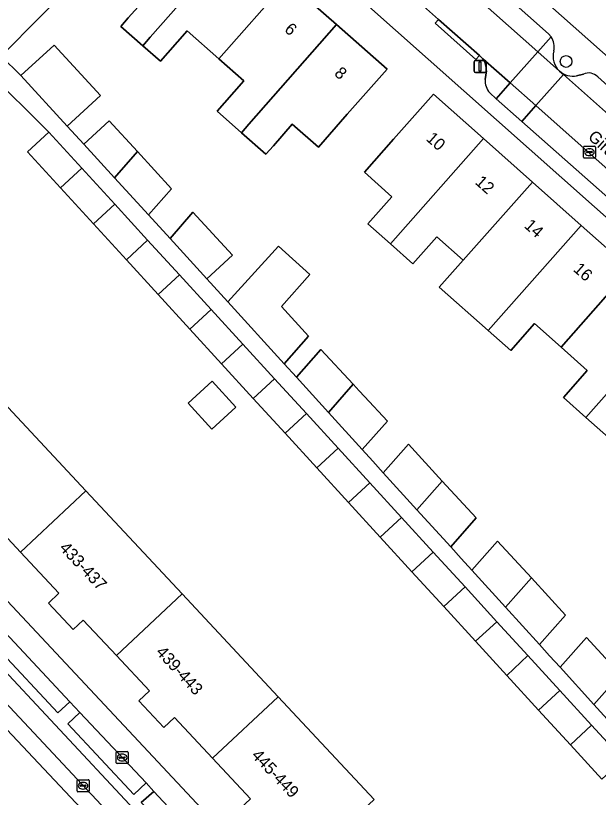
# Model space of a CAD drawing. Extents: x 163147 to 163550, y 380933 to 381639.
# Drawn here: x 163333 to 163381.5, y 381026.8 to 381091.7 of the extents above; entities that cross this region are included whole.
import ezdxf

# ---------------------------------------------------------------- set-up
doc = ezdxf.new("R2010")
doc.units = 0
for name, color, linetype in [('IMGEO_Berm_groen', 7, 'Continuous'), ('IMGEO_Boom', 7, 'Continuous'), ('IMGEO_Erf', 7, 'Continuous'), ('IMGEO_Fietspad_gesloten', 7, 'Continuous'), ('IMGEO_Kolk', 7, 'Continuous'), ('IMGEO_Lichtmast', 7, 'Continuous'), ('IMGEO_Openbare_ruimte_label', 7, 'Continuous'), ('IMGEO_Pand', 7, 'Continuous'), ('IMGEO_Pand_nummerreeks', 7, 'Continuous'), ('IMGEO_Parkeervlak_open', 7, 'Continuous'), ('IMGEO_Rijbaan_lokaal_gesloten', 7, 'Continuous'), ('IMGEO_Rijbaan_lokaal_open', 7, 'Continuous'), ('IMGEO_Voetpad_open', 7, 'Continuous')]:
    doc.layers.add(name, color=color, linetype=linetype)

msp = doc.modelspace()

# ---------------------------------------------------------------- linework, layer by layer
at = {"layer": 'IMGEO_Berm_groen'}
msp.add_lwpolyline([(163330.888, 381039.205), (163331.213, 381038.824), (163331.547, 381039.08), (163336.526, 381033.765), (163337.548, 381034.692), (163326.013, 381046.997)], dxfattribs=at)
for points in [[(163338.375, 381033.79), (163337.38, 381032.862), (163342.851, 381027.002), (163343.87, 381027.948)], [(163344.515, 381027.25), (163343.471, 381026.337), (163347.031, 381022.522), (163348.067, 381023.459)]]:
    msp.add_lwpolyline(points, close=True, dxfattribs=at)
at = {"layer": 'IMGEO_Boom'}
msp.add_circle((163378.776, 381087.858), 0.489, dxfattribs=at)
at = {"layer": 'IMGEO_Erf'}
for points in [[(163348.475, 381118.157), (163412.679, 381061.277), (163413.36, 381064.962), (163417.698, 381085.92), (163417.846, 381087.332), (163416.123, 381085.594), (163413.144, 381088.297), (163415.16, 381090.565), (163414.131, 381091.494), (163413.141, 381092.387), (163411.13, 381090.125), (163408.025, 381092.942), (163405.283, 381095.431), (163407.28, 381097.676), (163404.687, 381100.016), (163402.696, 381097.778), (163397.399, 381102.584), (163394.382, 381105.322), (163396.345, 381107.544), (163395.338, 381108.453), (163394.328, 381109.364), (163392.37, 381107.148), (163389.354, 381109.884)], [(163430.25, 381032.233), (163348.313, 381104.939), (163331.837, 381088.308), (163333.467, 381086.693), (163336.232, 381089.226), (163340.081, 381085.022), (163337.316, 381082.489), (163338.69, 381080.991), (163340.809, 381082.934), (163343.154, 381080.377), (163345.983, 381077.292), (163344.075, 381075.12), (163345.862, 381073.171), (163347.771, 381075.343), (163351.052, 381071.765), (163348.934, 381069.822), (163350.666, 381067.909), (163354.867, 381072.511), (163357.472, 381070.168), (163355.138, 381067.521), (163357.381, 381065.055), (163355.349, 381062.761), (163356.361, 381061.648), (163358.4, 381063.95), (163361.091, 381061.051), (163361.587, 381060.513), (163362.025, 381060.038), (163363.922, 381057.978), (163361.838, 381055.626), (163362.702, 381054.676), (163363.586, 381053.704), (163365.68, 381056.068), (163368.491, 381053.016), (163371.314, 381049.951), (163369.185, 381047.549), (163370.056, 381046.591), (163370.936, 381045.623), (163373.076, 381048.037), (163375.889, 381044.982), (163378.733, 381041.894), (163376.56, 381039.44), (163377.41, 381038.506), (163378.274, 381037.556), (163380.458, 381040.021), (163383.287, 381036.948)], [(163381.753, 381028.252), (163379.129, 381031.116), (163376.494, 381033.993), (163373.847, 381036.882), (163371.254, 381039.713), (163368.606, 381042.603), (163365.959, 381045.492), (163363.327, 381048.366), (163360.694, 381051.239), (163358.062, 381054.112), (163355.423, 381056.993), (163352.785, 381059.872), (163350.147, 381062.752), (163347.508, 381065.632), (163344.871, 381068.511), (163342.234, 381071.389), (163339.496, 381074.378), (163336.759, 381077.366), (163334.022, 381080.354), (163335.792, 381081.975), (163330.63, 381087.089)], [(163382.293, 381056.632), (163380.425, 381058.292), (163378.555, 381059.952), (163380.539, 381062.191), (163378.353, 381064.145), (163376.159, 381066.094), (163374.17, 381063.849), (163372.301, 381065.509), (163368.238, 381069.118), (163370.229, 381071.362), (163368.036, 381073.31), (163366.047, 381071.065), (163364.178, 381072.725), (163362.309, 381074.385), (163364.298, 381076.631), (163362.014, 381078.66), (163364.444, 381081.399), (163367.761, 381085.139), (163371.914, 381081.455), (163375.978, 381077.849), (163380.041, 381074.245), (163384.106, 381070.638)], [(163330.871, 381060.763), (163338.872, 381052.207), (163346.873, 381043.65), (163354.856, 381035.112), (163362.831, 381026.582)]]:
    msp.add_lwpolyline(points, dxfattribs=at)
for points in [[(163358.198, 381080.749), (163356.026, 381082.658), (163354.449, 381080.863), (163353.835, 381080.164), (163351.809, 381081.943), (163349.777, 381083.729), (163350.394, 381084.431), (163351.995, 381086.253), (163349.921, 381088.076), (163347.275, 381090.401), (163345.676, 381088.581), (163345.057, 381087.876), (163343.596, 381089.159), (163341.77, 381090.764), (163342.391, 381091.471), (163344.009, 381093.312), (163341.641, 381095.393), (163347.291, 381101.823), (163351.485, 381098.137), (163355.592, 381094.529), (163359.698, 381090.921), (163363.895, 381087.233), (163360.595, 381083.477)], [(163347.36, 381059.482), (163349.367, 381061.32), (163351.344, 381059.162), (163349.337, 381057.324)]]:
    msp.add_lwpolyline(points, close=True, dxfattribs=at)
at = {"layer": 'IMGEO_Fietspad_gesloten'}
for points in [[(163431.634, 380936.983), (163426.381, 380942.59), (163389.734, 380981.756), (163386.168, 380985.564), (163372.648, 381000), (163319.829, 381056.397), (163310.14, 381066.773), (163306.558, 381070.608), (163278.278, 381100.892), (163188.415, 381197.241)], [(163300.254, 381074.541), (163308.689, 381065.5), (163311.897, 381062.058), (163312.543, 381061.369), (163314.772, 381058.98), (163315.706, 381057.986), (163318.395, 381055.109), (163325.365, 381047.696), (163326.013, 381046.997), (163337.548, 381034.692), (163338.375, 381033.79), (163343.87, 381027.948), (163344.515, 381027.25), (163348.067, 381023.459), (163348.514, 381022.981), (163356.522, 381014.433), (163357.127, 381013.723), (163365.262, 381005.053), (163366.186, 381004.068), (163370.003, 381000), (163371.64, 380998.255), (163372.278, 380997.54), (163377.885, 380991.559)]]:
    msp.add_lwpolyline(points, dxfattribs=at)
at = {"layer": 'IMGEO_Kolk'}
for p, q in [((163380.216, 381079.904), (163380.216, 381080.756)), ((163380.291, 381080.83), (163381.143, 381080.83)), ((163380.704, 381080.61), (163380.729, 381080.61)), ((163381.217, 381080.756), (163381.217, 381079.904)), ((163381.143, 381079.83), (163380.291, 381079.83)), ((163380.475, 381080.324), (163380.475, 381080.336)), ((163380.913, 381080.287), (163380.515, 381080.287)), ((163380.518, 381080.373), (163380.916, 381080.373)), ((163380.727, 381080.05), (163380.702, 381080.05)), ((163380.959, 381080.336), (163380.959, 381080.324)), ((163341.386, 381029.629), (163341.386, 381030.481)), ((163341.461, 381030.555), (163342.313, 381030.555)), ((163342.387, 381030.481), (163342.387, 381029.629)), ((163341.645, 381030.049), (163341.645, 381030.061)), ((163342.083, 381030.012), (163341.685, 381030.012)), ((163341.688, 381030.098), (163342.086, 381030.098)), ((163341.897, 381029.775), (163341.872, 381029.775)), ((163341.874, 381030.335), (163341.899, 381030.335)), ((163342.129, 381030.061), (163342.129, 381030.049)), ((163342.313, 381029.555), (163341.461, 381029.555)), ((163338.132, 381027.293), (163338.132, 381028.145)), ((163338.207, 381028.219), (163339.059, 381028.219)), ((163338.62, 381027.999), (163338.645, 381027.999)), ((163339.133, 381028.145), (163339.133, 381027.293)), ((163339.059, 381027.219), (163338.207, 381027.219)), ((163338.391, 381027.713), (163338.391, 381027.725)), ((163338.829, 381027.676), (163338.431, 381027.676)), ((163338.434, 381027.762), (163338.832, 381027.762)), ((163338.643, 381027.439), (163338.618, 381027.439)), ((163338.875, 381027.725), (163338.875, 381027.713))]:
    msp.add_line(p, q, dxfattribs=at)
for points in [[(163380.216, 381079.904), (163380.216, 381080.756)], [(163380.291, 381080.83), (163381.143, 381080.83)], [(163381.217, 381080.756), (163381.217, 381079.904)], [(163381.143, 381079.83), (163380.291, 381079.83)], [(163341.386, 381029.629), (163341.386, 381030.481)], [(163341.461, 381030.555), (163342.313, 381030.555)], [(163342.387, 381030.481), (163342.387, 381029.629)], [(163342.313, 381029.555), (163341.461, 381029.555)], [(163338.132, 381027.293), (163338.132, 381028.145)], [(163338.207, 381028.219), (163339.059, 381028.219)], [(163339.133, 381028.145), (163339.133, 381027.293)], [(163339.059, 381027.219), (163338.207, 381027.219)]]:
    msp.add_lwpolyline(points, dxfattribs=at)
for centre, radius, start, end in [((163380.293, 381080.754), 0.0765, 91.55205, 178.44795), ((163380.293, 381080.754), 0.0765, 91.55205, 178.44795), ((163381.141, 381080.754), 0.0765, 1.55205, 88.44795), ((163381.141, 381080.754), 0.0765, 1.55205, 88.44795), ((163380.293, 381079.906), 0.0765, 181.55205, 268.44795), ((163380.293, 381079.906), 0.0765, 181.55205, 268.44795), ((163380.515, 381080.333), 0.0403, 85.87752, 175.75265), ((163380.512, 381080.323), 0.0366, 178.93798, 274.71019), ((163380.916, 381080.33), 0.043, 264.86636, 352.45326), ((163380.92, 381080.335), 0.0386, 1.73085, 96.63898), ((163381.141, 381079.906), 0.0765, 271.55205, 358.44795), ((163381.141, 381079.906), 0.0765, 271.55205, 358.44795), ((163341.463, 381030.479), 0.0765, 91.55205, 178.44795), ((163341.463, 381030.479), 0.0765, 91.55205, 178.44795), ((163342.311, 381030.479), 0.0765, 1.55205, 88.44795), ((163342.311, 381030.479), 0.0765, 1.55205, 88.44795), ((163341.685, 381030.058), 0.0403, 85.87752, 175.75265), ((163341.682, 381030.048), 0.0366, 178.93798, 274.71019), ((163342.086, 381030.055), 0.043, 264.86636, 352.45326), ((163342.09, 381030.06), 0.0386, 1.73085, 96.63898), ((163341.463, 381029.631), 0.0765, 181.55205, 268.44795), ((163341.463, 381029.631), 0.0765, 181.55205, 268.44795), ((163342.311, 381029.631), 0.0765, 271.55205, 358.44795), ((163342.311, 381029.631), 0.0765, 271.55205, 358.44795), ((163338.209, 381028.143), 0.0765, 91.55205, 178.44795), ((163338.209, 381028.143), 0.0765, 91.55205, 178.44795), ((163339.057, 381028.143), 0.0765, 1.55205, 88.44795), ((163339.057, 381028.143), 0.0765, 1.55205, 88.44795), ((163338.209, 381027.295), 0.0765, 181.55205, 268.44795), ((163338.209, 381027.295), 0.0765, 181.55205, 268.44795), ((163338.431, 381027.722), 0.0403, 85.87752, 175.75265), ((163338.428, 381027.712), 0.0366, 178.93798, 274.71019), ((163338.832, 381027.719), 0.043, 264.86636, 352.45326), ((163338.836, 381027.724), 0.0386, 1.73085, 96.63898), ((163339.057, 381027.295), 0.0765, 271.55205, 358.44795), ((163339.057, 381027.295), 0.0765, 271.55205, 358.44795)]:
    msp.add_arc(centre, radius, start, end, dxfattribs=at)
for centre, major_axis, ratio, start_param, end_param in [((163380.703, 381080.33), (-0.387, 0.002), 0.722429, 4.712389, 7.853982), ((163380.728, 381080.33), (-0.39, 0.002), 0.717154, 1.570796, 4.712389), ((163341.873, 381030.055), (-0.387, 0.002), 0.722429, 4.712389, 7.853982), ((163341.898, 381030.055), (-0.39, 0.002), 0.717154, 1.570796, 4.712389), ((163338.619, 381027.719), (-0.387, 0.002), 0.722429, 4.712389, 7.853982), ((163338.644, 381027.719), (-0.39, 0.002), 0.717154, 1.570796, 4.712389)]:
    msp.add_ellipse(centre, major_axis=major_axis, ratio=ratio, start_param=start_param, end_param=end_param, dxfattribs=at)
at = {"layer": 'IMGEO_Lichtmast'}
for p, q in [((163371.134, 381087.042), (163371.134, 381087.842)), ((163371.134, 381087.842), (163371.134, 381087.042)), ((163371.234, 381087.942), (163372.024, 381087.942)), ((163372.024, 381087.942), (163371.234, 381087.942)), ((163372.124, 381087.842), (163372.124, 381087.042)), ((163372.124, 381087.042), (163372.124, 381087.842)), ((163372.024, 381086.942), (163371.234, 381086.942)), ((163371.234, 381086.942), (163372.024, 381086.942))]:
    msp.add_line(p, q, dxfattribs=at)
msp.add_lwpolyline([(163371.554, 381087.817), (163371.704, 381087.817), (163371.704, 381087.067), (163371.554, 381087.067), (163371.554, 381087.817)], dxfattribs=at)
for centre, start, end in [((163371.234, 381087.842), 90, 180), ((163371.234, 381087.842), 90, 180), ((163372.024, 381087.842), 0, 90), ((163372.024, 381087.842), 360, 90), ((163371.234, 381087.042), 180, 270), ((163371.234, 381087.042), 180, 270), ((163372.024, 381087.042), 270, 0), ((163372.024, 381087.042), 270, 0)]:
    msp.add_arc(centre, 0.1, start, end, dxfattribs=at)
at = {"layer": 'IMGEO_Pand'}
for points in [[(163351.485, 381098.137), (163347.291, 381101.823), (163341.641, 381095.393), (163344.009, 381093.312), (163342.391, 381091.471), (163341.77, 381090.764), (163343.596, 381089.159), (163344.217, 381089.866)], [(163355.592, 381094.529), (163351.485, 381098.137), (163344.217, 381089.866), (163343.596, 381089.159), (163345.057, 381087.876), (163345.676, 381088.581), (163347.275, 381090.401), (163349.921, 381088.076)], [(163359.698, 381090.921), (163355.592, 381094.529), (163349.921, 381088.076), (163351.995, 381086.253), (163350.394, 381084.431), (163349.777, 381083.729), (163351.809, 381081.943), (163352.425, 381082.644)], [(163363.895, 381087.233), (163359.698, 381090.921), (163352.425, 381082.644), (163351.809, 381081.943), (163353.835, 381080.164), (163354.449, 381080.863), (163356.026, 381082.658), (163358.198, 381080.749), (163360.595, 381083.477)], [(163337.316, 381082.489), (163340.081, 381085.022), (163336.232, 381089.226), (163333.467, 381086.693)], [(163371.914, 381081.455), (163367.761, 381085.139), (163364.444, 381081.399), (163362.014, 381078.66), (163364.298, 381076.631), (163362.309, 381074.385), (163364.178, 381072.725)], [(163338.69, 381080.991), (163341.246, 381078.204), (163343.154, 381080.377), (163340.809, 381082.934)], [(163338.529, 381078.987), (163335.792, 381081.975), (163334.022, 381080.354), (163336.759, 381077.366)], [(163371.914, 381081.455), (163364.178, 381072.725), (163366.047, 381071.065), (163368.036, 381073.31), (163370.229, 381071.362), (163375.978, 381077.849)], [(163343.154, 381080.377), (163341.246, 381078.204), (163344.075, 381075.12), (163345.983, 381077.292)], [(163338.529, 381078.987), (163336.759, 381077.366), (163339.496, 381074.378), (163341.265, 381076)], [(163380.041, 381074.245), (163375.978, 381077.849), (163370.229, 381071.362), (163368.238, 381069.118), (163372.301, 381065.509)], [(163343.987, 381073.029), (163341.265, 381076), (163339.496, 381074.378), (163342.234, 381071.389)], [(163345.862, 381073.171), (163348.934, 381069.822), (163351.052, 381071.765), (163347.771, 381075.343)], [(163378.353, 381064.145), (163384.106, 381070.638), (163380.041, 381074.245), (163372.301, 381065.509), (163374.17, 381063.849), (163376.159, 381066.094)], [(163343.987, 381073.029), (163342.234, 381071.389), (163344.871, 381068.511), (163346.641, 381070.132)], [(163355.349, 381062.761), (163357.381, 381065.055), (163355.138, 381067.521), (163357.472, 381070.168), (163354.867, 381072.511), (163350.666, 381067.909)], [(163347.508, 381065.632), (163349.278, 381067.253), (163346.641, 381070.132), (163344.871, 381068.511)], [(163388.17, 381067.033), (163384.106, 381070.638), (163378.353, 381064.145), (163380.539, 381062.191), (163378.555, 381059.952), (163380.425, 381058.292)], [(163347.508, 381065.632), (163350.147, 381062.752), (163351.9, 381064.392), (163349.278, 381067.253)], [(163392.234, 381063.427), (163388.17, 381067.033), (163380.425, 381058.292), (163382.293, 381056.632), (163384.486, 381054.683), (163386.476, 381056.929)], [(163352.785, 381059.872), (163354.555, 381061.494), (163351.9, 381064.392), (163350.147, 381062.752)], [(163356.361, 381061.648), (163359.025, 381058.719), (163361.091, 381061.051), (163358.4, 381063.95)], [(163347.36, 381059.482), (163349.337, 381057.324), (163351.344, 381059.162), (163349.367, 381061.32)], [(163355.423, 381056.993), (163357.193, 381058.614), (163354.555, 381061.494), (163352.785, 381059.872)], [(163361.091, 381061.051), (163359.025, 381058.719), (163361.838, 381055.626), (163363.922, 381057.978), (163362.025, 381060.038), (163361.587, 381060.513)], [(163333.43, 381047.117), (163338.872, 381052.207), (163330.871, 381060.763), (163325.396, 381055.643), (163328.142, 381052.706), (163327.264, 381051.885), (163329.318, 381049.688), (163330.229, 381050.54)], [(163355.423, 381056.993), (163358.062, 381054.112), (163359.826, 381055.74), (163357.193, 381058.614)], [(163358.062, 381054.112), (163360.694, 381051.239), (163362.465, 381052.859), (163359.826, 381055.74)], [(163363.586, 381053.704), (163366.379, 381050.633), (163368.491, 381053.016), (163365.68, 381056.068)], [(163363.327, 381048.366), (163365.095, 381049.989), (163362.465, 381052.859), (163360.694, 381051.239)], [(163368.491, 381053.016), (163366.379, 381050.633), (163369.185, 381047.549), (163371.314, 381049.951)], [(163333.43, 381047.117), (163336.63, 381043.695), (163335.755, 381042.877), (163337.807, 381040.681), (163338.657, 381041.476), (163341.405, 381038.537), (163346.873, 381043.65), (163338.872, 381052.207)], [(163363.327, 381048.366), (163365.959, 381045.492), (163367.727, 381047.115), (163365.095, 381049.989)], [(163370.936, 381045.623), (163373.733, 381042.549), (163375.889, 381044.982), (163373.076, 381048.037)], [(163365.959, 381045.492), (163368.606, 381042.603), (163370.376, 381044.224), (163367.727, 381047.115)], [(163375.889, 381044.982), (163373.733, 381042.549), (163376.56, 381039.44), (163378.733, 381041.894)], [(163371.254, 381039.713), (163373.023, 381041.334), (163370.376, 381044.224), (163368.606, 381042.603)], [(163349.398, 381030.01), (163354.856, 381035.112), (163346.873, 381043.65), (163341.405, 381038.537), (163344.153, 381035.598), (163343.274, 381034.776), (163345.357, 381032.548), (163346.247, 381033.38)], [(163375.6, 381038.522), (163373.023, 381041.334), (163371.254, 381039.713), (163373.847, 381036.882)], [(163378.274, 381037.556), (163381.086, 381034.464), (163383.287, 381036.948), (163380.458, 381040.021)], [(163375.6, 381038.522), (163373.847, 381036.882), (163376.494, 381033.993), (163378.264, 381035.614)], [(163383.287, 381036.948), (163381.086, 381034.464), (163383.872, 381031.401), (163386.09, 381033.904)], [(163379.129, 381031.116), (163380.899, 381032.738), (163378.264, 381035.614), (163376.494, 381033.993)], [(163349.398, 381030.01), (163352.55, 381026.639), (163351.626, 381025.775), (163353.708, 381023.549), (163354.593, 381024.376), (163357.335, 381021.443), (163362.831, 381026.582), (163354.856, 381035.112)], [(163379.129, 381031.116), (163381.753, 381028.252), (163383.507, 381029.891), (163380.899, 381032.738)]]:
    msp.add_lwpolyline(points, close=True, dxfattribs=at)
at = {"layer": 'IMGEO_Parkeervlak_open'}
for points in [[(163359.851, 381103.345), (163376.424, 381088.651), (163377.537, 381089.906), (163377.316, 381090.152), (163362.865, 381103.01)], [(163377.537, 381089.906), (163376.424, 381088.651), (163378.234, 381087.046)], [(163372.431, 381085.248), (163372.977, 381084.764), (163374.14, 381086.075), (163371.869, 381088.089)], [(163372.153, 381087.08), (163372.041, 381086.371)], [(163378.234, 381087.046), (163378.55, 381086.767), (163384.78, 381081.243)], [(163380.213, 381086.796), (163379.652, 381086.677)], [(163384.173, 381084.084), (163381.403, 381086.575)], [(163386.023, 381075.538), (163376.265, 381084.191), (163375.103, 381082.881), (163383.185, 381075.72)], [(163317.29, 381050.513), (163364.587, 381000), (163377.34, 380986.38)], [(163348.277, 381019.96), (163330.88, 381038.568)]]:
    msp.add_lwpolyline(points, dxfattribs=at)
msp.add_lwpolyline([(163375.103, 381082.881), (163376.265, 381084.191), (163374.14, 381086.075), (163372.977, 381084.764)], close=True, dxfattribs=at)
for centre, radius, start, end in [((163376.333, 381089.08), 1.46, 346.37955, 34.44554), ((163379.388, 381088.289), 1.696, 164.71974, 227.11731), ((163370.258, 381087.091), 1.895, 359.66853, 31.77176), ((163379.332, 381088.356), 1.71, 230.03822, 280.78913), ((163380.663, 381085.903), 1, 42.24149, 116.71694), ((163373.562, 381086.27), 1.525, 176.20352, 222.09907)]:
    msp.add_arc(centre, radius, start, end, dxfattribs=at)
at = {"layer": 'IMGEO_Rijbaan_lokaal_gesloten'}
msp.add_lwpolyline([(163224.239, 381147.157), (163352.566, 381010.865), (163426.034, 380932.648), (163426.972, 380933.374), (163422.924, 380937.67), (163422.094, 380938.572), (163420.941, 380939.796), (163409.396, 380952.093), (163401.186, 380960.886), (163388.886, 380973.983), (163385.374, 380977.709), (163378.305, 380985.296), (163377.772, 380985.918), (163377.34, 380986.38), (163364.587, 381000), (163317.29, 381050.513), (163315.186, 381052.783), (163313.128, 381055.003), (163312.964, 381055.179), (163310.91, 381057.369), (163306.317, 381062.264), (163305.819, 381062.795), (163299.374, 381069.695)], dxfattribs=at)
at = {"layer": 'IMGEO_Rijbaan_lokaal_open'}
msp.add_lwpolyline([(163351.292, 381106.335), (163354.767, 381103.254), (163365.924, 381093.36), (163368.184, 381091.357), (163371.576, 381088.351), (163371.869, 381088.089), (163374.14, 381086.075), (163376.424, 381088.651), (163359.851, 381103.345), (163359.545, 381103.611), (163357.625, 381105.319), (163346.989, 381114.749)], dxfattribs=at)
for points in [[(163378.55, 381086.767), (163378.234, 381087.046), (163376.424, 381088.651), (163374.14, 381086.075), (163376.265, 381084.191)], [(163384.971, 381081.074), (163384.78, 381081.243), (163378.55, 381086.767), (163376.265, 381084.191), (163386.023, 381075.538), (163387.932, 381073.845), (163402.686, 381060.759), (163402.997, 381060.496), (163406.637, 381057.379), (163408.848, 381059.9), (163408.639, 381060.085), (163389.921, 381076.681), (163388.332, 381078.092)]]:
    msp.add_lwpolyline(points, close=True, dxfattribs=at)
at = {"layer": 'IMGEO_Voetpad_open'}
for points in [[(163429.339, 381046.517), (163420.6, 381054.259), (163418.735, 381055.912), (163415.366, 381058.896), (163413.645, 381060.421), (163412.679, 381061.277), (163348.475, 381118.157)], [(163354.767, 381103.254), (163351.292, 381106.335), (163348.313, 381104.939), (163430.25, 381032.233), (163431.364, 381035.276), (163430.742, 381035.835), (163427.947, 381038.346), (163425.074, 381040.927), (163424.908, 381041.074)], [(163314.628, 381076.045), (163310.339, 381071.71), (163312.93, 381069.222), (163330.63, 381087.089), (163331.837, 381088.308), (163348.313, 381104.939)], [(163362.865, 381103.01), (163377.316, 381090.152), (163377.537, 381089.906)], [(163367.902, 381091.03), (163368.184, 381091.357), (163365.924, 381093.36)], [(163371.869, 381088.089), (163371.576, 381088.351), (163371.288, 381088.025), (163367.902, 381091.03)], [(163383.872, 381031.401), (163381.086, 381034.464), (163378.274, 381037.556), (163377.41, 381038.506), (163376.56, 381039.44), (163373.733, 381042.549), (163370.936, 381045.623), (163370.056, 381046.591), (163369.185, 381047.549), (163366.379, 381050.633), (163363.586, 381053.704), (163362.702, 381054.676), (163361.838, 381055.626), (163359.025, 381058.719), (163356.361, 381061.648), (163355.349, 381062.761), (163350.666, 381067.909), (163348.934, 381069.822), (163345.862, 381073.171), (163344.075, 381075.12), (163341.246, 381078.204), (163338.69, 381080.991), (163337.316, 381082.489), (163333.467, 381086.693), (163331.837, 381088.308)], [(163330.63, 381087.089), (163335.792, 381081.975), (163338.529, 381078.987), (163341.265, 381076), (163343.987, 381073.029), (163346.641, 381070.132), (163349.278, 381067.253), (163351.9, 381064.392), (163354.555, 381061.494), (163357.193, 381058.614), (163359.826, 381055.74), (163362.465, 381052.859), (163365.095, 381049.989), (163367.727, 381047.115), (163370.376, 381044.224), (163373.023, 381041.334), (163375.6, 381038.522), (163378.264, 381035.614), (163380.899, 381032.738), (163383.507, 381029.891)], [(163372.041, 381086.371), (163372.153, 381087.08)], [(163379.652, 381086.677), (163380.213, 381086.796)], [(163381.403, 381086.575), (163384.173, 381084.084)], [(163383.185, 381075.72), (163375.103, 381082.881), (163372.977, 381084.764), (163372.431, 381085.248)], [(163319.829, 381056.397), (163372.648, 381000)], [(163352.55, 381026.639), (163349.398, 381030.01), (163346.247, 381033.38), (163345.357, 381032.548), (163343.274, 381034.776), (163344.153, 381035.598), (163341.405, 381038.537), (163338.657, 381041.476), (163337.807, 381040.681), (163335.755, 381042.877), (163336.63, 381043.695), (163333.43, 381047.117), (163330.229, 381050.54)]]:
    msp.add_lwpolyline(points, dxfattribs=at)
for points in [[(163371.576, 381088.351), (163368.184, 381091.357), (163367.902, 381091.03), (163371.288, 381088.025)], [(163344.515, 381027.25), (163343.87, 381027.948), (163342.851, 381027.002), (163337.38, 381032.862), (163338.375, 381033.79), (163337.548, 381034.692), (163336.526, 381033.765), (163331.547, 381039.08), (163331.213, 381038.824), (163330.88, 381038.568), (163348.277, 381019.96), (163348.609, 381020.284), (163348.877, 381020.544), (163347.451, 381022.072), (163348.514, 381022.981), (163348.067, 381023.459), (163347.031, 381022.522), (163343.471, 381026.337)]]:
    msp.add_lwpolyline(points, close=True, dxfattribs=at)
for centre, radius, start, end in [((163376.333, 381089.08), 1.46, 346.37955, 34.44554), ((163379.388, 381088.289), 1.696, 164.71974, 227.11731), ((163370.258, 381087.091), 1.895, 359.66853, 31.77176), ((163379.332, 381088.356), 1.71, 230.03822, 280.78913), ((163380.663, 381085.903), 1, 42.24149, 116.71694), ((163373.562, 381086.27), 1.525, 176.20352, 222.09907)]:
    msp.add_arc(centre, radius, start, end, dxfattribs=at)

# ---------------------------------------------------------------- texts
at = {"layer": 'IMGEO_Openbare_ruimte_label'}
msp.add_text('Giraffestraat', height=1, rotation=318.24275, dxfattribs=at).set_placement((163380.523, 381081.5))
at = {"layer": 'IMGEO_Pand_nummerreeks'}
for s, rotation, p in [('6', 318.69547, (163355.297, 381090.422)), ('8', 318.69547, (163359.451, 381086.771)), ('10', 318.42122, (163367.075, 381081.363)), ('12', 318.42122, (163371.147, 381077.751)), ('14', 318.42045, (163375.226, 381074.132)), ('16', 318.42122, (163379.303, 381070.515)), ('433-437', 313.35297, (163336.608, 381047.409)), ('439-443', 312.60639, (163344.631, 381038.763)), ('445-449', 313.54978, (163352.571, 381030.176))]:
    msp.add_text(s, height=1, rotation=rotation, dxfattribs=at).set_placement(p)

doc.saveas('drawing.dxf')
